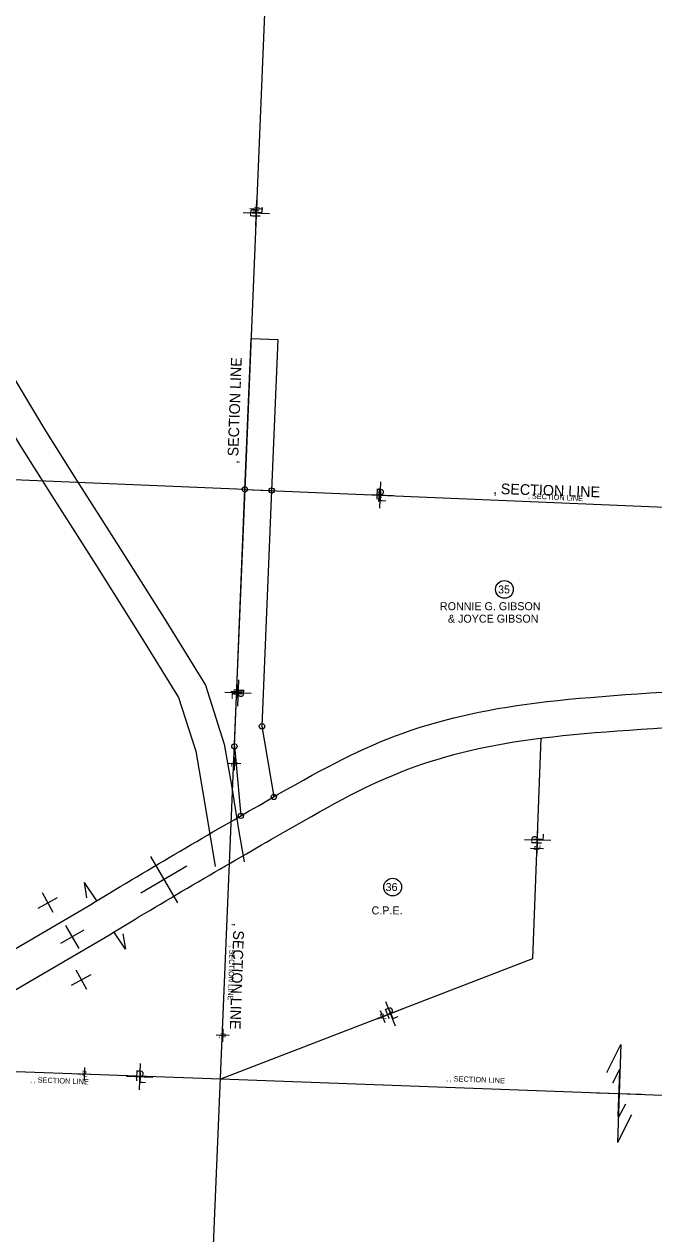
# Model space of a CAD drawing. Extents: x 2814293 to 2835768, y 121185 to 156337.
# Drawn here: x 2822904 to 2824318, y 131914 to 134634 of the extents above; entities that cross this region are included whole.
import ezdxf

# ---------------------------------------------------------------- set-up
doc = ezdxf.new("R2010")
doc.units = 0
for name, color, linetype in [('Default', 7, 'Continuous'), ('Roadway-Ditches', 7, 'Continuous'), ('Roadway-Edge of pavement', 7, 'Continuous'), ('Roadway-Edge of shoulder', 7, 'Continuous'), ('Roadway-Entrances', 7, 'Continuous'), ('Roadway-Existing Easement', 7, 'Continuous'), ('Roadway-New rw', 7, 'Continuous'), ('Roadway-Safety', 7, 'Continuous'), ('Roadway-Temporary easement', 7, 'Continuous'), ('Roadway-Walls', 7, 'Continuous'), ('Scratch-2', 7, 'Continuous'), ('Scratch-5', 7, 'Continuous'), ('Text-New rw label', 7, 'Continuous'), ('Traffic_Control-Traffic barriers', 7, 'Continuous')]:
    doc.layers.add(name, color=color, linetype=linetype)

msp = doc.modelspace()

# ---------------------------------------------------------------- linework, layer by layer
at = {"layer": 'Default'}
for p, q in [((2823187.5, 132762.6), (2823247.8, 132658.9)), ((2823269.5, 132740.9), (2823165.8, 132680.6)), ((2822934.9, 132646.7), (2822978.7, 132670.9)), ((2822968.8, 132636.9), (2822944.7, 132680.7)), ((2823037.5, 132597.1), (2822985.6, 132566.9)), ((2822996.5, 132607.9), (2823026.6, 132556.1)), ((2823044.4, 132463.7), (2823020.2, 132507.5)), ((2823010.4, 132473.5), (2823054.2, 132497.7))]:
    msp.add_line(p, q, dxfattribs=at)
at = {"layer": 'Roadway-Ditches'}
for centre in [(2823982.5, 133363.3), (2823731.5, 132694)]:
    msp.add_circle(centre, 20, dxfattribs=at)
at = {"layer": 'Roadway-Edge of pavement'}
for p, q in [((2823044.4, 132670), (2823039, 132704.6)), ((2823066.8, 132663.2), (2823039, 132704.6)), ((2823131.1, 132554.7), (2823105.4, 132593)), ((2823125.7, 132589.2), (2823131.1, 132554.7)), ((2824226.1, 132253.6), (2824242, 132284.7)), ((2824242, 132284.7), (2824238.2, 132174.8)), ((2824239.2, 132204.8), (2824241, 132254.7)), ((2824215.1, 132230.6), (2824265.1, 132228.9)), ((2824240.1, 132229.8), (2824240.1, 132229.8)), ((2824254.1, 132206), (2824238.2, 132174.8))]:
    msp.add_line(p, q, dxfattribs=at)
at = {"layer": 'Roadway-Edge of shoulder'}
for p, q in [((2823424.1, 134180.1), (2823426.1, 134239)), ((2823395.7, 134210.6), (2823454.5, 134208.5)), ((2823704.1, 133604.8), (2823701.9, 133545.9)), ((2823673.6, 133576.5), (2823732.4, 133574.2)), ((2823384.9, 133159.6), (2823382.9, 133100.7)), ((2823413.3, 133129.1), (2823354.4, 133131.2)), ((2824056.2, 132770.5), (2824057.7, 132829.4)), ((2824027.5, 132800.7), (2824086.4, 132799.2)), ((2823715.3, 132436.7), (2823737.2, 132382)), ((2823698.9, 132398.4), (2823753.6, 132420.4)), ((2823164.4, 132297.1), (2823162.1, 132238.2)), ((2823133.8, 132268.8), (2823192.7, 132266.5))]:
    msp.add_line(p, q, dxfattribs=at)
at = {"layer": 'Roadway-Entrances'}
for p, q in [((2823507.8, 136237.3), (2823399.5, 133588.1)), ((2823399.5, 133588.1), (2822068.5, 133644.1)), ((2823399.5, 133588.1), (2823288.6, 130934)), ((2823399.5, 133588.1), (2826050.7, 133475.8)), ((2824046.3, 132533.6), (2824065.4, 133029)), ((2823345.6, 132262.5), (2824046.3, 132533.6)), ((2822012.3, 132311.3), (2823345.6, 132262.5)), ((2823345.6, 132262.5), (2826003.4, 132165.2))]:
    msp.add_line(p, q, dxfattribs=at)
at = {"layer": 'Roadway-Existing Easement'}
for points in [[(2822160.1, 135001.6), (2822561.8, 134515.3), (2822613.4, 134435.4), (2822681.9, 134329.2), (2822719, 134240.3), (2822750.8, 134154.7), (2822781.5, 134073.7), (2822818.7, 133977.3), (2822854.4, 133882.2), (2822951.6, 133719.6), (2823021.3, 133609.2), (2823072.9, 133528.1), (2823120.1, 133454), (2823221.9, 133292.4), (2823310.9, 133147.7), (2823353.3, 133015.4), (2823369.6, 132922.1), (2823386.3, 132818.9), (2823397.7, 132751.1)], [(2822105.7, 134963.9), (2822508.4, 134476.2), (2822558, 134399.6), (2822623.3, 134298.3), (2822657.6, 134216.1), (2822689, 134131.5), (2822719.9, 134050.1), (2822757, 133953.8), (2822794.7, 133853.4), (2822895.4, 133685), (2822965.6, 133573.8), (2823017.2, 133492.6), (2823064.4, 133418.6), (2823165.9, 133257.5), (2823250.4, 133119.9), (2823289.1, 132999.5), (2823304.5, 132911.2), (2823321.2, 132808.1), (2823332.7, 132740.1)]]:
    msp.add_lwpolyline(points, dxfattribs=at)
at = {"layer": 'Roadway-New rw'}
for p, q in [((2823376, 133010.6), (2823399.5, 133588.1)), ((2823399.5, 133588.1), (2823459.4, 133585.6)), ((2823459.4, 133585.6), (2823437.9, 133055.5)), ((2823437.9, 133055.5), (2823464.5, 132896.7)), ((2823376, 133010.6), (2823390.5, 132854.2))]:
    msp.add_line(p, q, dxfattribs=at)
at = {"layer": 'Roadway-Temporary easement'}
for p, q in [((2823399.5, 133588.1), (2823413.4, 133927.6)), ((2823413.4, 133927.6), (2823473.4, 133925.2)), ((2823473.4, 133925.2), (2823459.4, 133585.6))]:
    msp.add_line(p, q, dxfattribs=at)
at = {"layer": 'Roadway-Walls'}
for p, q in [((2823440.2, 134218.1), (2823410.7, 134219.1)), ((2823426, 134233.3), (2823424.9, 134203.9)), ((2823685.5, 133576.3), (2823714.9, 133575.2)), ((2823700.8, 133590.4), (2823699.6, 133561)), ((2823397.1, 133132.6), (2823367.6, 133133.6)), ((2823382.9, 133147.8), (2823381.8, 133118.4)), ((2823390.4, 132971.1), (2823361, 132972.1)), ((2823376.2, 132986.3), (2823375.2, 132956.9)), ((2824041.1, 132781.7), (2824070.6, 132781)), ((2824055.5, 132766.6), (2824056.2, 132796.1)), ((2823695, 132397.5), (2823722.4, 132408.5)), ((2823703.2, 132416.7), (2823714.2, 132389.3)), ((2823350.1, 132375.5), (2823349.1, 132346.1)), ((2823364.3, 132360.3), (2823334.9, 132361.3)), ((2823039.6, 132288.6), (2823038.5, 132259.2)), ((2823024.3, 132274.4), (2823053.8, 132273.3))]:
    msp.add_line(p, q, dxfattribs=at)
at = {"layer": 'Scratch-2'}
for p, q in [((2824212.2, 132277.3), (2824244, 132339.7)), ((2824244, 132339.7), (2824236.2, 132119.8)), ((2824238.3, 132179.8), (2824241.9, 132279.7)), ((2824190.1, 132231.5), (2824290.1, 132228)), ((2824240.1, 132229.8), (2824240.1, 132229.8)), ((2824268, 132182.2), (2824236.2, 132119.8))]:
    msp.add_line(p, q, dxfattribs=at)
at = {"layer": 'Text-New rw label'}
for centre in [(2823399.5, 133588.1), (2823459.4, 133585.6), (2823437.9, 133055.5), (2823376, 133010.6), (2823464.5, 132896.7), (2823390.5, 132854.2)]:
    msp.add_circle(centre, 6, dxfattribs=at)
at = {"layer": 'Traffic_Control-Traffic barriers'}
msp.add_line((2822437.5, 132294.6), (2823054.8, 132655.8), dxfattribs=at)
msp.add_lwpolyline([(2822475.3, 132229.8), (2822525.9, 132253.6), (2823095.2, 132586.8)], dxfattribs=at)
for points in [[(2823053.4, 132655), (2823168, 132725.3), (2823464.1, 132897.3), (2823711.6, 133038), (2824012.7, 133114.5), (2824432.4, 133136.2), (2824988.1, 133180.8), (2825241.8, 133126.7), (2825483.3, 133082.4), (2825627.1, 133071.4), (2825695.3, 133072.2)], [(2823095.2, 132586.8), (2823209, 132656.6), (2823504, 132827.9), (2823741.8, 132963.1), (2824024.8, 133035), (2824437.7, 133056.4), (2824982.9, 133100.2), (2825226.3, 133048.2), (2825473, 133003), (2825624.5, 132991.4), (2825696.2, 132992.2)]]:
    msp.add_open_spline(points, degree=3, dxfattribs=at)

# ---------------------------------------------------------------- texts
at = {"layer": 'Roadway-Ditches'}
for s, p in [('35', (2823968.2, 133354.2)), ('RONNIE G. GIBSON', (2823837.6, 133316.4)), ('& JOYCE GIBSON', (2823855.6, 133288.4)), ('36', (2823715.6, 132685)), ('C.P.E.', (2823684.1, 132632.5))]:
    msp.add_text(s, height=18, rotation=0.038, dxfattribs=at).set_placement(p)
at = {"layer": 'Roadway-Edge of shoulder'}
for s, rotation, p in [('L', 87.9775, (2823438.9, 134206.4)), ('P', 87.9775, (2823434.3, 134198.5)), ('P', 357.7804, (2823692, 133566.2)), ('L', 357.7804, (2823699.8, 133561.6)), ('P', 267.9775, (2823374.6, 133141.2)), ('L', 267.9775, (2823370.1, 133133.3)), ('P', 88.5164, (2824066.3, 132789.1)), ('L', 88.5164, (2824070.8, 132796.9)), ('P', 21.8729, (2823719.9, 132396.5)), ('L', 21.8729, (2823728.9, 132395.5)), ('P', 357.7804, (2823152.2, 132258.4)), ('L', 357.7804, (2823160, 132253.8))]:
    msp.add_text(s, height=23.6, rotation=rotation, dxfattribs=at).set_placement(p)
at = {"layer": 'Roadway-Safety'}
for s, rotation, p in [('‚ SECTION LINE', 357.1103, (2824035.7, 133567.8)), ('‚ SECTION LINE', 267.9775, (2823365.3, 132562.4)), ('‚ ‚ SECTION LINE', 357.7804, (2822917.3, 132255.2)), ('‚ ‚ SECTION LINE', 357.7804, (2823851.8, 132257.8))]:
    msp.add_text(s, height=12, rotation=rotation, dxfattribs=at).set_placement(p)
at = {"layer": 'Roadway-Walls'}
for s, rotation, p in [('L', 267.9775, (2823418.5, 134220.2)), ('P', 267.9775, (2823420.8, 134224.1)), ('P', 357.7804, (2823694.7, 133571.1)), ('L', 357.7804, (2823698.6, 133568.8)), ('L', 267.9775, (2823375.4, 133134.7)), ('P', 267.9775, (2823377.7, 133138.6)), ('L', 267.9775, (2823368.8, 132973.2)), ('P', 267.9775, (2823371.1, 132977.1)), ('P', 88.5164, (2824060.5, 132775.9)), ('L', 88.5164, (2824062.8, 132779.8)), ('P', 21.8729, (2823705.5, 132396.5)), ('L', 21.8729, (2823710, 132396)), ('L', 267.9775, (2823342.7, 132362.4)), ('P', 267.9775, (2823345, 132366.3)), ('P', 357.7804, (2823033.5, 132269.3)), ('L', 357.7804, (2823037.4, 132267))]:
    msp.add_text(s, height=11.8, rotation=rotation, dxfattribs=at).set_placement(p)
at = {"layer": 'Scratch-5'}
for rotation, p in [(87.9775, (2823384.1, 133646)), (358.1103, (2823958, 133578.1)), (267.9775, (2823374.1, 132613))]:
    msp.add_text('‚ SECTION LINE', height=24, rotation=rotation, dxfattribs=at).set_placement(p)

doc.saveas('drawing.dxf')
